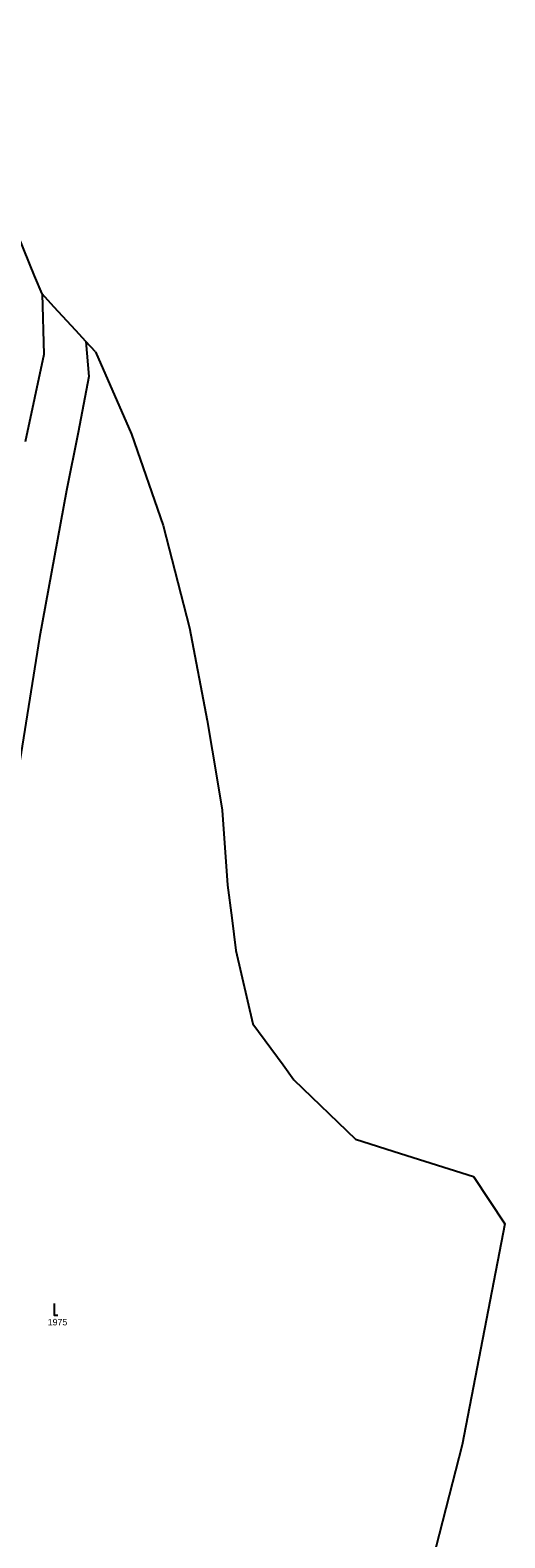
# Model space of a CAD drawing. Extents: x -802857 to -799647, y -1020285 to -1015884.
# Drawn here: x -801308.3 to -801185.1, y -1016562.1 to -1016170.3 of the extents above; entities that cross this region are included whole.
import ezdxf

# ---------------------------------------------------------------- set-up
doc = ezdxf.new("R2010")
doc.units = 0
for name, color, linetype in [('Default', 7, 'Continuous'), ('KN_HRANICE', 7, 'Continuous'), ('KN_KULTURY', 7, 'Continuous'), ('KN_PARCELY', 7, 'Continuous')]:
    doc.layers.add(name, color=color, linetype=linetype)

# ---------------------------------------------------------------- blocks, each defined once
blk = doc.blocks.new('302')
at = {"layer": 'Default'}
blk.add_lwpolyline([(0, 3), (0, 0), (1, 0)], dxfattribs=at)

msp = doc.modelspace()

# ---------------------------------------------------------------- linework, layer by layer
at = {"layer": 'KN_HRANICE'}
for p, q in [((-801307.14, -1016234.16), (-801333.2, -1016170.31)), ((-801305.22, -1016238.85), (-801307.14, -1016234.16)), ((-801305.22, -1016238.85), (-801304.79, -1016254.56)), ((-801302.16, -1016242.17), (-801305.22, -1016238.85)), ((-801296.43, -1016248.4), (-801302.16, -1016242.17)), ((-801293.82, -1016251.23), (-801296.43, -1016248.4)), ((-801293.82, -1016251.23), (-801293.03, -1016260.34)), ((-801291.35, -1016253.92), (-801293.82, -1016251.23)), ((-801304.79, -1016254.56), (-801309.62, -1016277.26)), ((-801291.35, -1016253.92), (-801281.96, -1016275.28)), ((-801293.03, -1016260.34), (-801295.86, -1016274.86)), ((-801295.86, -1016274.86), (-801298.85, -1016289.93)), ((-801281.96, -1016275.28), (-801273.73, -1016298.99)), ((-801298.85, -1016289.93), (-801305.9, -1016328.14)), ((-801273.73, -1016298.99), (-801266.91, -1016325.63)), ((-801266.91, -1016325.63), (-801262.33, -1016349.67)), ((-801305.9, -1016328.14), (-801311.92, -1016366.18)), ((-801262.33, -1016349.67), (-801259.75, -1016365.1)), ((-801259.75, -1016365.1), (-801258.44, -1016372.97)), ((-801258.44, -1016372.97), (-801257.05, -1016392.52)), ((-801257.05, -1016392.52), (-801255.96, -1016400.96)), ((-801255.96, -1016400.96), (-801254.86, -1016409.5)), ((-801254.86, -1016409.5), (-801250.45, -1016428.49)), ((-801250.45, -1016428.49), (-801242.64, -1016439.22)), ((-801242.64, -1016439.22), (-801239.82, -1016443.1)), ((-801239.82, -1016443.1), (-801223.83, -1016458.49)), ((-801223.83, -1016458.49), (-801212.17, -1016462.19)), ((-801212.17, -1016462.19), (-801193.22, -1016468.21)), ((-801193.22, -1016468.21), (-801185.05, -1016480.49)), ((-801185.05, -1016480.49), (-801196.12, -1016537.94)), ((-801196.12, -1016537.94), (-801207.69, -1016582.91))]:
    msp.add_line(p, q, dxfattribs=at)

# ---------------------------------------------------------------- block references
at = {"layer": 'KN_KULTURY'}
msp.add_blockref('302', (-801302.09, -1016504.19), dxfattribs=at)

# ---------------------------------------------------------------- texts
at = {"layer": 'KN_PARCELY'}
msp.add_text('1975', height=1.7, dxfattribs=at).set_placement((-801303.73, -1016506.89))

doc.saveas('drawing.dxf')
